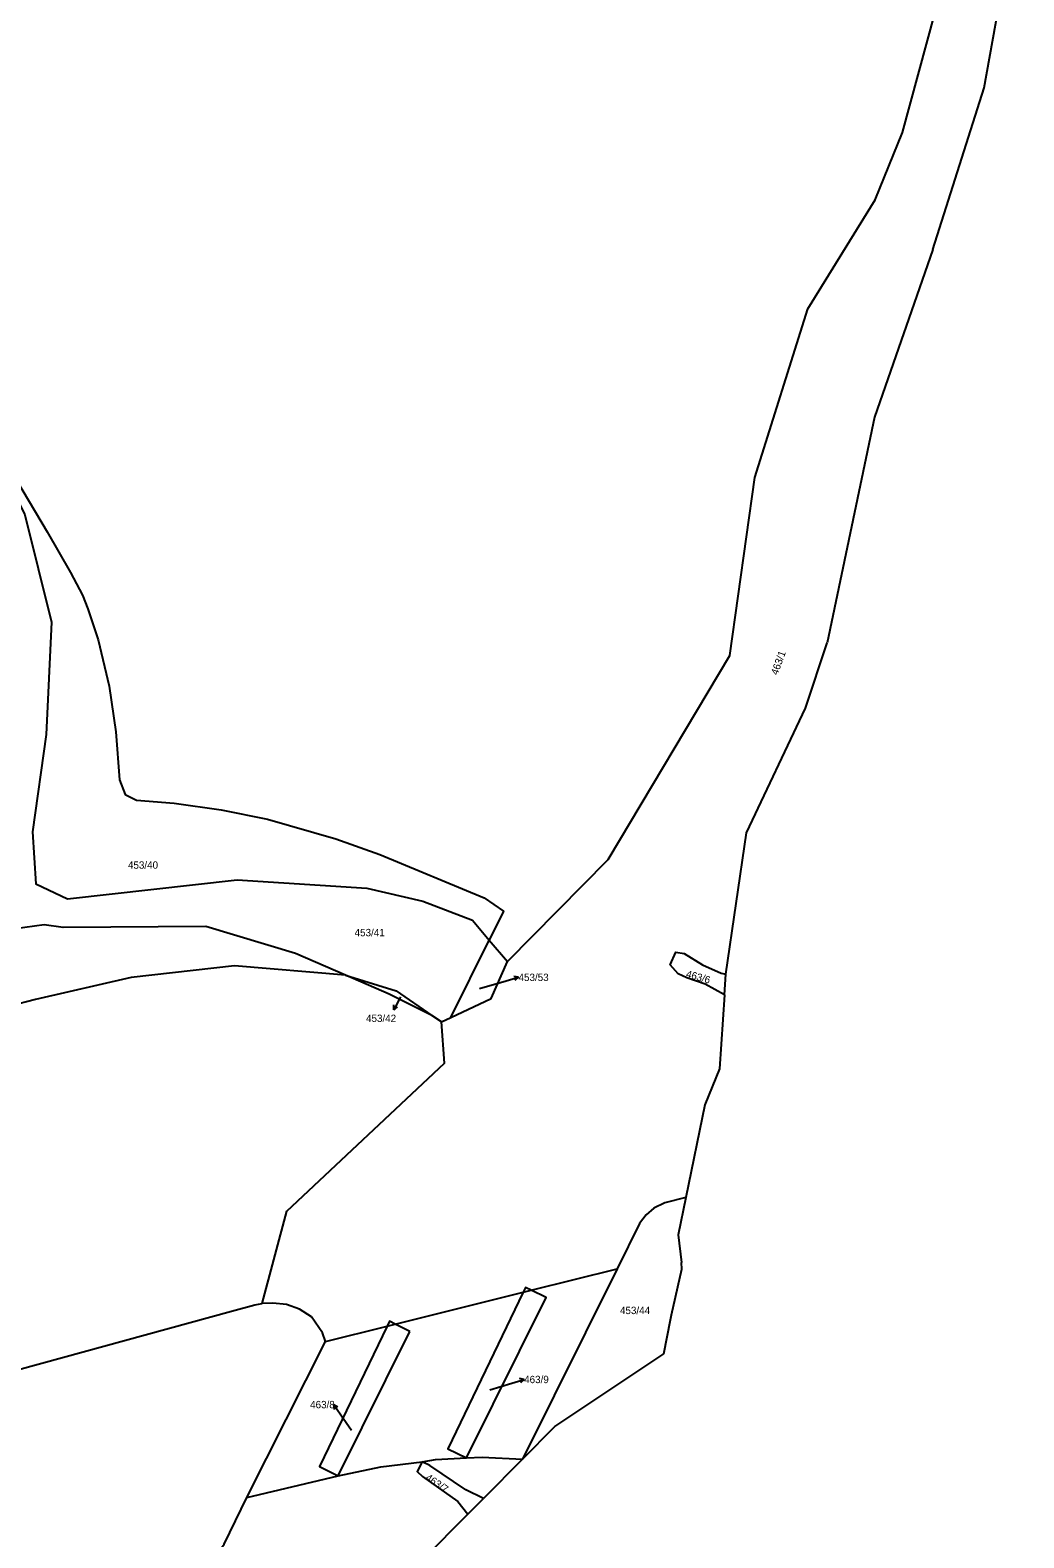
# Model space of a CAD drawing. Extents: x -882150 to -879379, y -1022570 to -1019819.
# Drawn here: x -879878.6 to -879649.2, y -1020796.9 to -1020448.8 of the extents above; entities that cross this region are included whole.
import ezdxf

# ---------------------------------------------------------------- set-up
doc = ezdxf.new("R2010")
doc.units = 0
for name, color, linetype in [('Hranice parcel', 7, 'Continuous'), ('Parcelní čísla', 7, 'Continuous'), ('Pop  PČ popisy', 7, 'Continuous'), ('Vnitřní kresba', 7, 'Continuous')]:
    doc.layers.add(name, color=color, linetype=linetype)

msp = doc.modelspace()

# ---------------------------------------------------------------- linework, layer by layer
at = {"layer": 'Hranice parcel'}
for p, q in [((-879670.16, -1020499.5), (-879658.32, -1020462.18)), ((-879670.16, -1020499.5), (-879683.62, -1020538.22)), ((-879683.62, -1020538.22), (-879694.55, -1020590.25)), ((-879699.54, -1020605.36), (-879694.55, -1020590.25)), ((-879781.51, -1020676.81), (-879772.63, -1020658.91)), ((-879772.63, -1020658.91), (-879768.43, -1020663.89)), ((-879805.81, -1020667.04), (-879817.33, -1020662)), ((-879795.71, -1020671.4), (-879805.81, -1020667.04)), ((-879719.05, -1020666.51), (-879717.95, -1020666.81)), ((-879718.27, -1020671.54), (-879717.95, -1020666.81)), ((-879785.84, -1020676.31), (-879795.71, -1020671.4)), ((-879718.27, -1020671.54), (-879719.44, -1020688.66)), ((-879783.66, -1020677.82), (-879785.84, -1020676.31)), ((-879783.66, -1020677.82), (-879781.51, -1020676.81)), ((-879719.44, -1020688.66), (-879722.85, -1020696.91)), ((-879722.85, -1020696.91), (-879727.24, -1020718.31)), ((-879728.17, -1020734.89), (-879728.18, -1020733.35)), ((-879730.5, -1020745.4), (-879728.17, -1020734.89)), ((-879732.3, -1020754.41), (-879730.72, -1020746.62)), ((-879730.72, -1020746.62), (-879730.5, -1020745.4)), ((-879757.48, -1020771.24), (-879732.3, -1020754.41)), ((-879764.9, -1020778.72), (-879757.48, -1020771.24)), ((-879764.9, -1020778.72), (-879773.93, -1020787.81)), ((-879777.54, -1020791.45), (-879773.93, -1020787.81))]:
    msp.add_line(p, q, dxfattribs=at)
for points in [[(-879658.32, -1020462.18), (-879652.92, -1020432.12), (-879649.15, -1020404.38)], [(-879768.43, -1020663.89), (-879745.16, -1020640.29), (-879717.06, -1020593.24), (-879711.31, -1020552.11), (-879699.06, -1020513.18), (-879683.46, -1020488.01), (-879677.18, -1020472.46), (-879667.75, -1020437.8)], [(-879888.6, -1020543.4), (-879887.68, -1020542.9), (-879874.66, -1020564.64), (-879869.28, -1020574.02), (-879866.55, -1020579.31), (-879865.33, -1020582.41), (-879862.95, -1020589.58), (-879860.41, -1020600.26), (-879858.85, -1020610.83), (-879857.98, -1020621.89), (-879856.66, -1020625.28), (-879854.09, -1020626.63), (-879845.37, -1020627.31), (-879834.53, -1020628.82), (-879823.81, -1020631.02), (-879808.01, -1020635.54), (-879797.85, -1020639.13), (-879773.76, -1020649.14), (-879769.33, -1020652.27), (-879772.63, -1020658.91)], [(-879888.6, -1020543.4), (-879887.69, -1020544.98), (-879879.83, -1020560.74), (-879873.67, -1020585.51), (-879874.91, -1020611.47), (-879878.08, -1020633.92), (-879877.33, -1020645.9), (-879869.99, -1020649.38), (-879830.84, -1020645.01), (-879800.86, -1020646.94), (-879787.95, -1020649.9), (-879776.47, -1020654.35), (-879772.63, -1020658.91)], [(-879717.95, -1020666.81), (-879713.22, -1020634.17), (-879699.54, -1020605.36)], [(-879817.33, -1020662), (-879838.04, -1020655.79), (-879870.99, -1020656.01), (-879875.36, -1020655.41), (-879891.09, -1020657.52), (-879904.5, -1020660.66)], [(-879805.81, -1020667.04), (-879831.43, -1020664.89), (-879855.31, -1020667.58), (-879877.4, -1020672.6), (-879889.36, -1020675.71), (-879906.65, -1020682.99), (-879922.47, -1020691.94), (-879963.22, -1020718.34), (-880007.29, -1020745.44)], [(-879781.51, -1020676.81), (-879772.17, -1020672.41), (-879768.43, -1020663.89)], [(-879718.27, -1020671.54), (-879722.74, -1020669.12), (-879726.98, -1020667.6), (-879728.97, -1020666.68), (-879730.85, -1020664.63), (-879729.52, -1020661.67), (-879727.56, -1020662.04), (-879723.34, -1020664.63), (-879719.05, -1020666.51)], [(-879805.81, -1020667.04), (-879794.09, -1020670.61), (-879785.84, -1020676.31)], [(-879825.01, -1020742.84), (-879819.35, -1020721.5), (-879782.93, -1020687.3), (-879783.66, -1020677.82)], [(-879727.24, -1020718.31), (-879732.04, -1020719.55), (-879734.62, -1020720.84), (-879736.38, -1020722.34), (-879737.9, -1020724.35), (-879743.03, -1020734.84), (-879764.9, -1020778.72)], [(-879727.24, -1020718.31), (-879729.01, -1020726.94), (-879728.18, -1020733.35)], [(-879762.91, -1020739.77), (-879764.23, -1020739.12), (-879764.76, -1020740.23), (-879782.18, -1020776.36), (-879777.87, -1020778.47), (-879759.47, -1020741.45), (-879762.91, -1020739.77)], [(-879891.14, -1020760.75), (-879832.12, -1020744.62), (-879826.76, -1020743.13), (-879825.01, -1020742.84)], [(-879855.67, -1020806.93), (-879849.12, -1020805.59), (-879840.65, -1020803.59), (-879838.63, -1020802.86), (-879836.73, -1020801.7), (-879835.11, -1020800.17), (-879833.86, -1020798.37), (-879828.56, -1020787.58), (-879810.46, -1020751.56), (-879811.09, -1020749.56), (-879813.66, -1020745.92), (-879816.39, -1020744.12), (-879819.42, -1020743.08), (-879822.57, -1020742.71), (-879825.01, -1020742.84)], [(-879790.92, -1020749.24), (-879794.35, -1020747.57), (-879795.68, -1020746.92), (-879796.21, -1020748.03), (-879811.81, -1020780.46), (-879807.51, -1020782.57), (-879790.92, -1020749.24)], [(-879773.93, -1020787.81), (-879778.03, -1020785.84), (-879786.32, -1020780.24), (-879788.07, -1020779.39), (-879789.23, -1020781.63), (-879788.06, -1020782.72), (-879779.9, -1020788.51), (-879777.54, -1020791.45)], [(-879981.7, -1020969.74), (-879959.72, -1020975.95), (-879934.19, -1020971.25), (-879911.49, -1020960.29), (-879889.63, -1020942.98), (-879866.16, -1020917.83), (-879837.52, -1020859.01), (-879808.19, -1020822.32), (-879777.54, -1020791.45)]]:
    msp.add_lwpolyline(points, dxfattribs=at)
at = {"layer": 'Pop  PČ popisy'}
for p, q in [((-879774.87, -1020670.08), (-879768.73, -1020668.33)), ((-879768.73, -1020668.33), (-879765.845, -1020667.503)), ((-879765.845, -1020667.503), (-879766.946, -1020667.298)), ((-879765.845, -1020667.503), (-879766.67, -1020668.26)), ((-879793.1, -1020672.04), (-879793.26, -1020672.33)), ((-879793.26, -1020672.33), (-879794.669, -1020674.98)), ((-879794.669, -1020674.98), (-879794.641, -1020673.86)), ((-879794.669, -1020674.98), (-879793.757, -1020674.331)), ((-879772.45, -1020762.74), (-879767.42, -1020761.22)), ((-879767.42, -1020761.22), (-879764.55, -1020760.343)), ((-879764.55, -1020760.343), (-879765.654, -1020760.157)), ((-879764.55, -1020760.343), (-879765.361, -1020761.114)), ((-879806.89, -1020768.6), (-879808.611, -1020766.142)), ((-879808.611, -1020766.142), (-879807.627, -1020766.675)), ((-879808.611, -1020766.142), (-879808.447, -1020767.249)), ((-879804.4, -1020772.15), (-879806.89, -1020768.6))]:
    msp.add_line(p, q, dxfattribs=at)
at = {"layer": 'Vnitřní kresba'}
for p, q in [((-879762.91, -1020739.77), (-879743.03, -1020734.84)), ((-879794.35, -1020747.57), (-879764.76, -1020740.23)), ((-879764.76, -1020740.23), (-879762.91, -1020739.77)), ((-879810.46, -1020751.56), (-879796.21, -1020748.03)), ((-879796.21, -1020748.03), (-879794.35, -1020747.57)), ((-879797.61, -1020780.52), (-879788.07, -1020779.39)), ((-879788.07, -1020779.39), (-879785.03, -1020778.81)), ((-879785.03, -1020778.81), (-879777.87, -1020778.47)), ((-879777.87, -1020778.47), (-879774.23, -1020778.32)), ((-879774.23, -1020778.32), (-879764.9, -1020778.72)), ((-879828.56, -1020787.58), (-879807.51, -1020782.57)), ((-879807.51, -1020782.57), (-879797.61, -1020780.52))]:
    msp.add_line(p, q, dxfattribs=at)

# ---------------------------------------------------------------- texts
at = {"layer": 'Parcelní čísla'}
for s, rotation, p in [('463/1', 70, (-879706.031, -1020597.85)), ('463/6', 344, (-879727.314, -1020667.437)), ('463/7', 326, (-879787.505, -1020783.414))]:
    msp.add_text(s, height=1.7, rotation=rotation, dxfattribs=at).set_placement(p)
for s, p in [('453/40', (-879856.04, -1020642.44)), ('453/41', (-879803.7, -1020658.03)), ('453/53', (-879765.84, -1020668.36)), ('453/42', (-879801.061, -1020677.818)), ('453/44', (-879742.42, -1020745.26)), ('463/9', (-879764.55, -1020761.2)), ('463/8', (-879813.972, -1020767))]:
    msp.add_text(s, height=1.7, dxfattribs=at).set_placement(p)

doc.saveas('drawing.dxf')
